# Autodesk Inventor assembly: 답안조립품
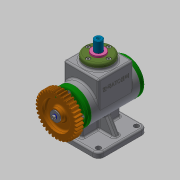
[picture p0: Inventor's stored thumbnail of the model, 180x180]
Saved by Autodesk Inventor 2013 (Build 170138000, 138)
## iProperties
Created: 2019-01
Part Number: 답안조립품
Document SubType Name: Assembly
Designer: Gpr
Mass: 1743.43 g
Surface Area: 1517.22 cm^2
Volume: 491.998 cm^3
Density: 3.54357 g/cm^3
Author: Gpr
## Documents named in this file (18)
- C:\Users\Administrator\Desktop\390107V1039\답안조립품.iam
- C:\Users\Administrator\Desktop\390107V1039\본체.ipt
- C:\Users\Administrator\Desktop\390107V1039\베어링 6203.ipt
- C:\Users\Administrator\Desktop\390107V1039\편심축.ipt
- C:\Users\Administrator\Desktop\390107V1039\앞커버.ipt
- C:\Users\Administrator\Desktop\390107V1039\뒤커버.ipt
- C:\Users\Administrator\Desktop\390107V1039\볼트 M4.ipt
- C:\Users\Administrator\Desktop\390107V1039\상부커버.ipt
- C:\Users\Administrator\Desktop\390107V1039\오일 실 17 30 5.ipt
- C:\Users\Administrator\Desktop\390107V1039\키 4x4x12.ipt
- C:\Users\Administrator\Desktop\390107V1039\스퍼기어.ipt
- C:\Users\Administrator\Desktop\390107V1039\평와셔.ipt
- C:\Users\Administrator\Desktop\390107V1039\스프링와셔.ipt
- C:\Users\Administrator\Desktop\390107V1039\부시.ipt
- C:\Users\Administrator\Desktop\390107V1039\멈춤링.ipt
- C:\Users\Administrator\Desktop\390107V1039\슬라이더.ipt
- C:\Users\Administrator\Desktop\390107V1039\스프링조립용 와셔.ipt
- C:\Users\Administrator\Desktop\390107V1039\가변스프링.ipt
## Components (1 placed, 1 different names)
1. 가변스프링:1
